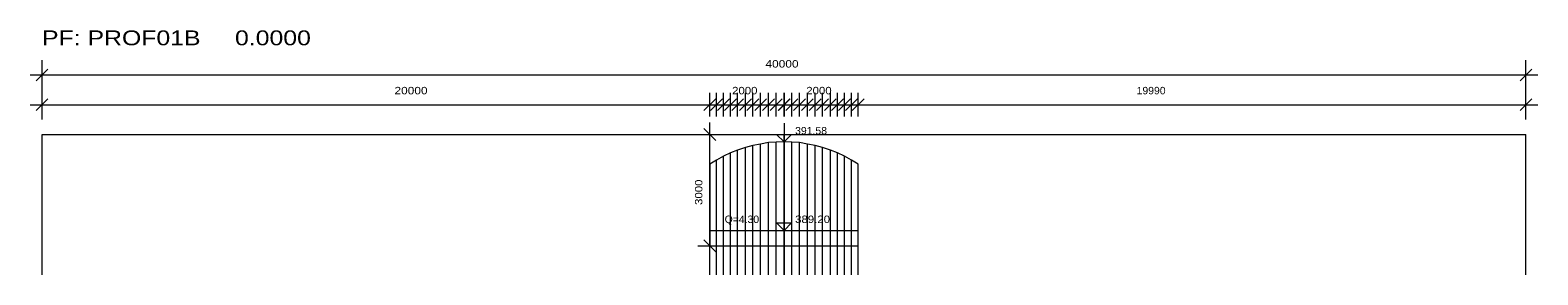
# Model space of a CAD drawing. Extents: x 7 to 442, y -393 to 441.
# Drawn here: x 401.72 to 442.36, y 395.97 to 402.55 of the extents above; entities that cross this region are included whole.
import ezdxf

# ---------------------------------------------------------------- set-up
doc = ezdxf.new("R2010")
doc.units = 0
doc.header["$LTSCALE"] = 0.08
doc.layers.add('7', color=7, linetype='Continuous', lineweight=13)

msp = doc.modelspace()

# ---------------------------------------------------------------- linework, layer by layer
at = {"layer": '7'}
for p, q in [((402.038, 400.146), (402.038, 401.746)), ((442.038, 400.146), (442.038, 401.746)), ((401.718, 401.346), (442.358, 401.346)), ((401.878, 401.186), (402.198, 401.506)), ((441.878, 401.186), (442.198, 401.506)), ((402.038, 400.226), (402.038, 400.866)), ((420.038, 400.226), (420.038, 400.866)), ((420.038, 400.226), (420.038, 400.866)), ((420.218, 400.226), (420.218, 400.866)), ((420.408, 400.226), (420.408, 400.866)), ((420.598, 400.226), (420.598, 400.866)), ((420.788, 400.226), (420.788, 400.866)), ((420.998, 400.226), (420.998, 400.866)), ((421.198, 400.226), (421.198, 400.866)), ((421.408, 400.226), (421.408, 400.866)), ((421.618, 400.226), (421.618, 400.866)), ((421.828, 400.226), (421.828, 400.866)), ((422.038, 400.226), (422.038, 400.866)), ((422.038, 400.226), (422.038, 400.866)), ((422.038, 400.226), (422.038, 400.866)), ((422.048, 400.226), (422.048, 400.866)), ((422.048, 400.226), (422.048, 400.866)), ((422.248, 400.226), (422.248, 400.866)), ((422.458, 400.226), (422.458, 400.866)), ((422.668, 400.226), (422.668, 400.866)), ((422.878, 400.226), (422.878, 400.866)), ((423.078, 400.226), (423.078, 400.866)), ((423.288, 400.226), (423.288, 400.866)), ((423.478, 400.226), (423.478, 400.866)), ((423.668, 400.226), (423.668, 400.866)), ((423.858, 400.226), (423.858, 400.866)), ((424.038, 400.226), (424.038, 400.866)), ((424.038, 400.226), (424.038, 400.866)), ((442.038, 400.226), (442.038, 400.866)), ((401.718, 400.546), (442.358, 400.546)), ((401.878, 400.386), (402.198, 400.706)), ((419.878, 400.386), (420.198, 400.706)), ((419.878, 400.386), (420.198, 400.706)), ((420.058, 400.386), (420.378, 400.706)), ((420.248, 400.386), (420.568, 400.706)), ((420.438, 400.386), (420.758, 400.706)), ((420.628, 400.386), (420.948, 400.706)), ((420.838, 400.386), (421.158, 400.706)), ((421.038, 400.386), (421.358, 400.706)), ((421.248, 400.386), (421.568, 400.706)), ((421.458, 400.386), (421.778, 400.706)), ((421.668, 400.386), (421.988, 400.706)), ((421.878, 400.386), (422.198, 400.706)), ((421.878, 400.386), (422.198, 400.706)), ((421.878, 400.386), (422.198, 400.706)), ((421.888, 400.386), (422.208, 400.706)), ((421.888, 400.386), (422.208, 400.706)), ((422.088, 400.386), (422.408, 400.706)), ((422.298, 400.386), (422.618, 400.706)), ((422.508, 400.386), (422.828, 400.706)), ((422.718, 400.386), (423.038, 400.706)), ((422.918, 400.386), (423.238, 400.706)), ((423.128, 400.386), (423.448, 400.706)), ((423.318, 400.386), (423.638, 400.706)), ((423.508, 400.386), (423.828, 400.706)), ((423.698, 400.386), (424.018, 400.706)), ((423.878, 400.386), (424.198, 400.706)), ((423.878, 400.386), (424.198, 400.706)), ((441.878, 400.386), (442.198, 400.706)), ((420.198, 399.586), (419.878, 399.906)), ((420.038, 396.586), (420.038, 400.066)), ((402.038, 395.966), (402.038, 399.746)), ((419.718, 399.746), (420.518, 399.746)), ((421.618, 395.966), (421.618, 399.526)), ((421.828, 395.966), (421.828, 399.536)), ((422.038, 395.966), (422.038, 399.746)), ((422.038, 395.966), (422.038, 399.546)), ((422.038, 399.546), (422.048, 399.546)), ((422.048, 395.966), (422.048, 399.746)), ((422.048, 395.966), (422.048, 399.546)), ((422.248, 395.966), (422.248, 399.536)), ((422.458, 395.966), (422.458, 399.526)), ((442.038, 395.966), (442.038, 399.746)), ((420.408, 395.966), (420.408, 399.156)), ((420.598, 395.966), (420.598, 399.246)), ((420.788, 395.966), (420.788, 399.326)), ((420.998, 395.966), (420.998, 399.396)), ((421.198, 395.966), (421.198, 399.446)), ((421.408, 395.966), (421.408, 399.486)), ((422.668, 395.966), (422.668, 399.486)), ((422.878, 395.966), (422.878, 399.446)), ((423.078, 395.966), (423.078, 399.396)), ((423.288, 395.966), (423.288, 399.326)), ((423.478, 395.966), (423.478, 399.246)), ((423.668, 395.966), (423.668, 399.156)), ((420.038, 395.966), (420.038, 398.946)), ((420.218, 395.966), (420.218, 399.056)), ((423.858, 395.966), (423.858, 399.056)), ((424.038, 395.966), (424.038, 398.946)), ((420.038, 397.161), (424.038, 397.161)), ((419.718, 396.746), (420.518, 396.746)), ((420.198, 396.586), (419.878, 396.906)), ((420.038, 395.966), (420.038, 396.746)), ((422.038, 395.966), (422.038, 396.746)), ((424.038, 395.966), (424.038, 396.746))]:
    msp.add_line(p, q, dxfattribs=at)
for points in [[(422.038, 400.046), (422.038, 399.546), (421.838, 399.746), (422.238, 399.746), (422.038, 399.546)], [(402.038, 399.746), (422.038, 399.746), (422.038, 399.546), (421.828, 399.536), (421.618, 399.526), (421.408, 399.486), (421.198, 399.446), (420.998, 399.396), (420.788, 399.326), (420.598, 399.246), (420.408, 399.156), (420.218, 399.056), (420.038, 398.946), (420.038, 396.746), (422.038, 396.746), (424.038, 396.746), (424.038, 398.946), (423.858, 399.056), (423.668, 399.156), (423.478, 399.246), (423.288, 399.326), (423.078, 399.396), (422.878, 399.446), (422.668, 399.486), (422.458, 399.526), (422.248, 399.536), (422.048, 399.546), (422.048, 399.746), (442.038, 399.746)], [(422.038, 397.661), (422.038, 397.161), (421.838, 397.361), (422.238, 397.361), (422.038, 397.161)]]:
    msp.add_lwpolyline(points, dxfattribs=at)

# ---------------------------------------------------------------- texts
for s, height, width, p in [('PF: PROF01B     0.0000', 0.4, 1.25, (402.038, 402.146)), ('40000', 0.2, 1.2, (421.538, 401.546)), ('20000', 0.2, 1.2, (411.538, 400.826)), ('2000', 0.2, 1.15, (420.638, 400.826)), ('2000', 0.2, 1.15, (422.638, 400.826)), ('19990', 0.2, 1.05, (431.543, 400.826)), ('391.58', 0.2, 1.05, (422.338, 399.746)), ('Q=4.30', 0.2, 1.05, (420.438, 397.361)), ('389.20', 0.2, 1.15, (422.338, 397.361))]:
    msp.add_text(s, height=height, dxfattribs=dict(at, width=width)).set_placement(p)
at = {"layer": '7', "width": 1.15}
msp.add_text('3000', height=0.2, rotation=90, dxfattribs=at).set_placement((419.838, 397.846))

doc.saveas('drawing.dxf')
